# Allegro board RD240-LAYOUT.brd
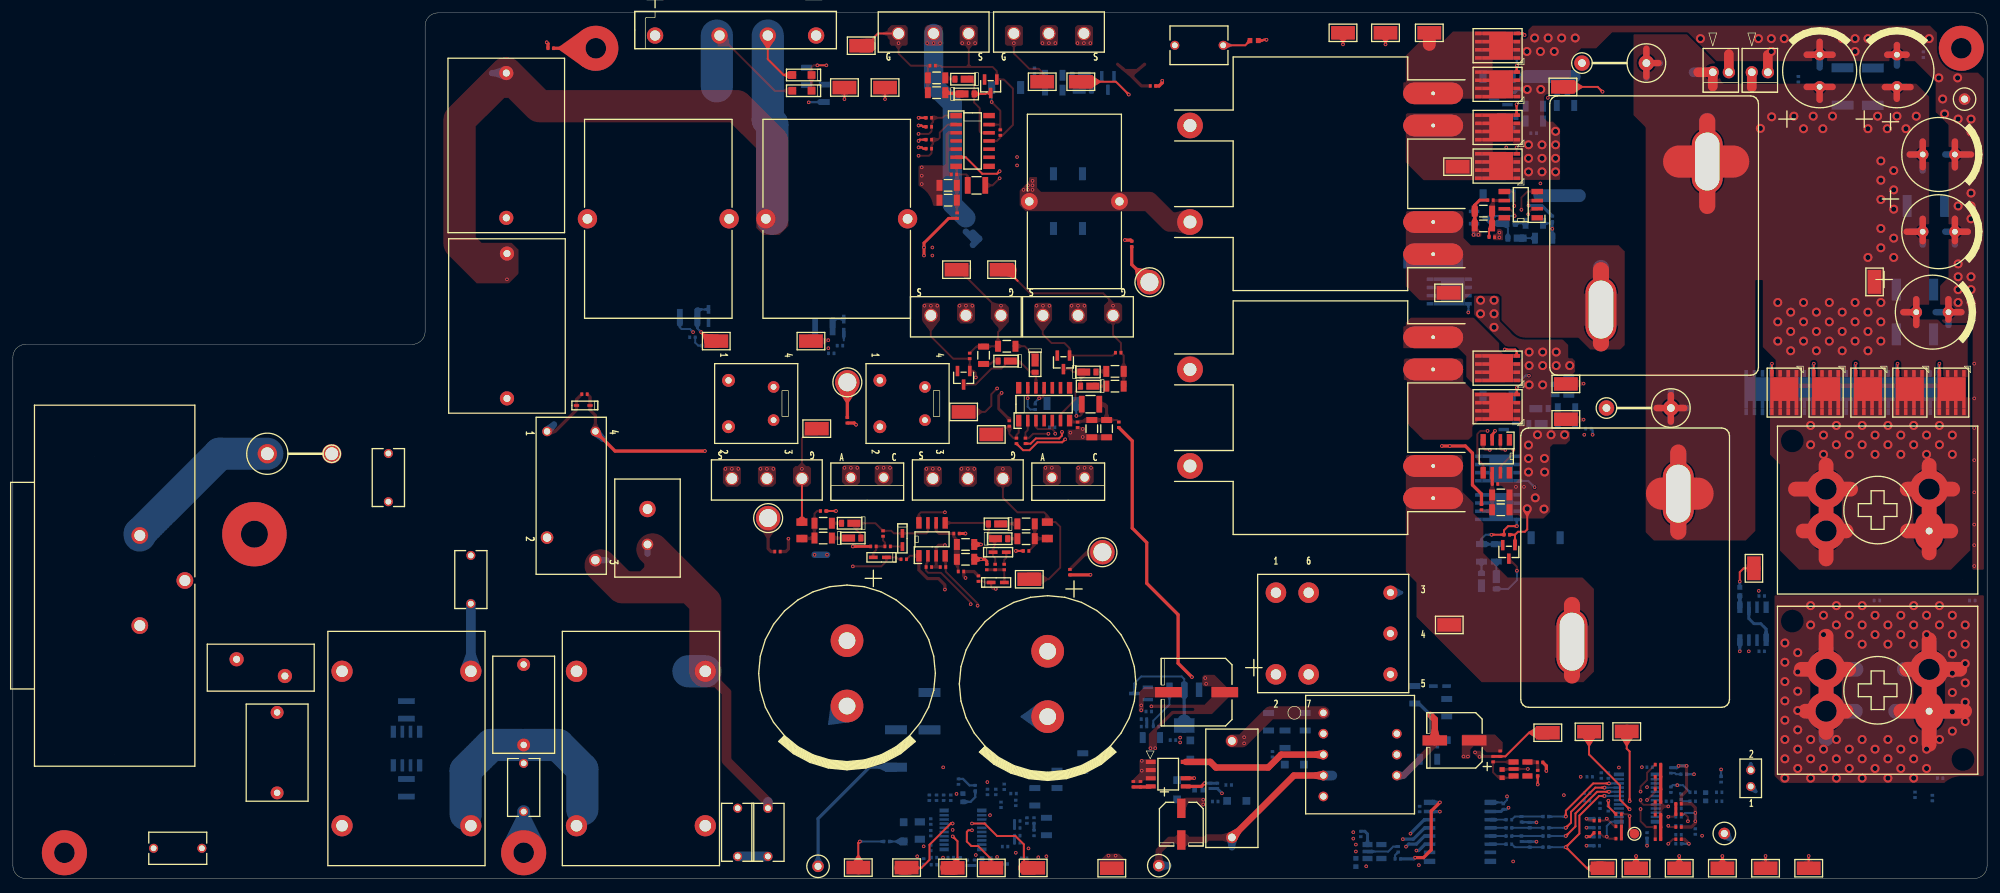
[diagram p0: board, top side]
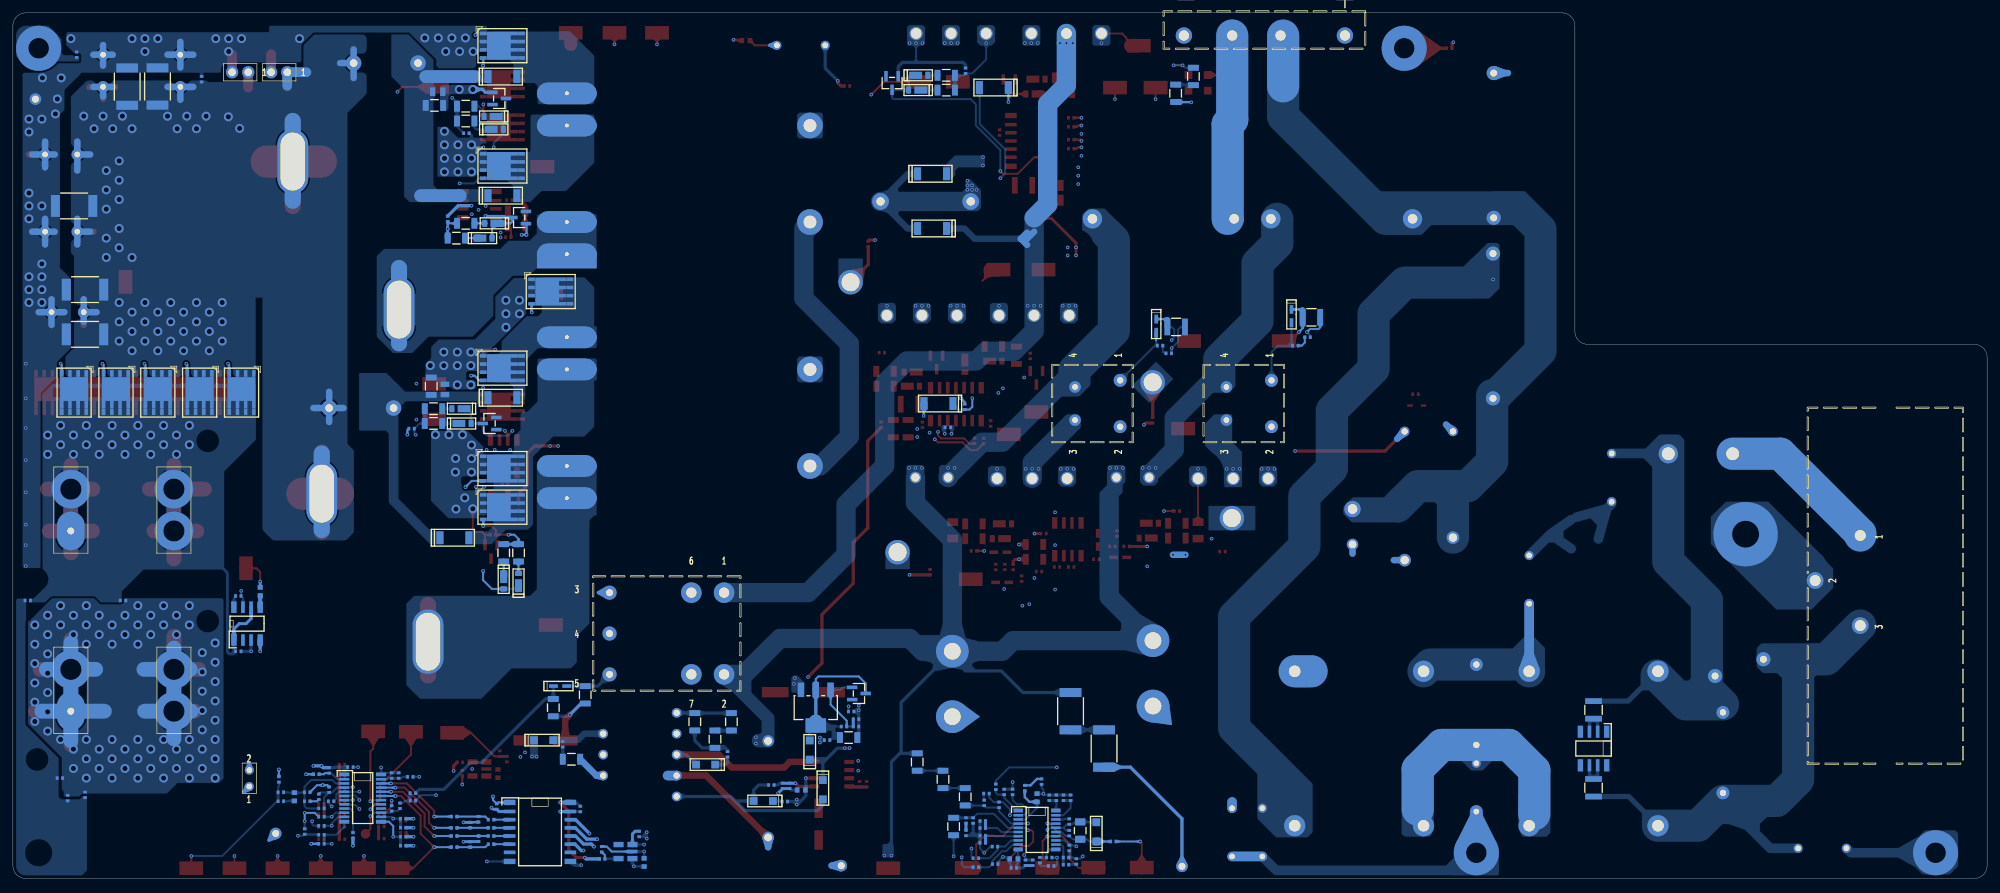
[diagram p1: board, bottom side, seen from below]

Outline 306.5 x 134.5 mm; copper layers: TOP, CONDUCTIVE2, CONDUCTIVE3, CONDUCTIVE4, CONDUCTIVE5, BOTTOM. Coordinates in mm from the lower left corner of the outline.
Outline path: 0,81 0.03,81.35 0.12,81.68 0.27,82 0.47,82.29 0.71,82.53 1,82.73 1.32,82.88 1.65,82.97 2,83 62,83 62.35,83.03 62.68,83.12 63,83.27 63.29,83.47 63.53,83.71 63.73,84 63.88,84.32 63.97,84.65 64,85 64,132.5 64.03,132.85 64.12,133.18 64.27,133.5 64.47,133.79 64.71,134.03 65,134.23 65.32,134.38 65.65,134.47 66,134.5 304.5,134.5 304.85,134.47 305.18,134.38 305.5,134.23 305.79,134.03 306.03,133.79 306.23,133.5 306.38,133.18 306.47,132.85 306.5,132.5 306.5,2 306.47,1.65 306.38,1.32 306.23,1 306.03,0.71 305.79,0.47 305.5,0.27 305.18,0.12 304.85,0.03 304.5,0 2,0 1.65,0.03 1.32,0.12 1,0.27 0.71,0.47 0.47,0.71 0.27,1 0.12,1.32 0.03,1.65 0,2 0,81

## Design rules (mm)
constraint set DEFAULT: 

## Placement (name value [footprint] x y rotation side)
C1  -  [LOCAL_DC215N]  160.65 25.15 90 top
C2  -  [FTP_13]  280.5 128 270 top
C3  -  [FTP_13]  292.5 128 270 top
C4  -  [FTP_13]  301.5 112.5 180 top
C5  -  [FTP_13]  301.5 100.5 180 top
C6  -  [FTP_13]  300.5 88 180 top
C7  -  [LOCAL_DC215N]  129.5 26.8 90 top
C18  -  [FTP_65]  153.3 115.9 90 top
C19  -  [FTP_65#2]  158.72 73.29 90 bottom
C20  -  [FTP_67#2]  262.8 12.7 90 bottom
C21  -  [FTP_65#2]  259 12.7 270 bottom
C22  -  [FTP_65#2]  258.6 10.9 0 bottom
C23  -  [FTP_65#2]  246.6 16 90 bottom
C24  -  [FTP_65#2]  247.7 16 90 bottom
C25  -  [FTP_65#2]  257.1 12 0 bottom
C26  -  [FTP_65#2]  247.7 10.9 90 bottom
C27  -  [DC810K]  240.55 122.25 180 bottom
C30  -  [FTP_73]  41.02 19.56 90 top
C31  -  [LOCAL_DE2E3SA222MN3AT02F]  79.3 10.4 90 top
C32  -  [LOCAL_DE2E3SA222MN3AT02F]  71.1 50.2 270 top
C33  -  [FTP_75]  76.6 113.9 270 top
C34  -  [FTP_65#2]  127.05 81.6 180 bottom
C35  -  [FTP_65]  151.2 48.4 270 top
C36  -  [FTP_65#2]  105.5 84.1 180 bottom
C37  -  [FTP_65]  133.6 51.6 0 top
C38  -  [FTP_65#2]  157.42 9.01 270 bottom
C39  -  [FTP_65#2]  153.4 11.45 90 bottom
C40  -  [FTP_67#2]  147.5 12.55 90 bottom
C41  -  [FTP_66]  149.4 14.05 90 bottom
C42  -  [FTP_65#2]  142.5 4.75 270 bottom
C43  -  [FTP_65#2]  143 3.25 180 bottom
C44  -  [FTP_65#2]  143 2.15 180 bottom
C45  -  [FTP_65#2]  145.6 3.25 180 bottom
C46  -  [FTP_65#2]  147.06 2.85 270 bottom
C47  -  [FTP_65#2]  142.5 7.05 90 bottom
C48  -  [FTP_24]  140.8 7.45 90 bottom
C49  -  [FTP_65#2]  142.5 8.85 270 bottom
C50  -  [FTP_65#2]  152.6 13.45 90 bottom
C51  -  [DC810K]  239.43 76 90 bottom
C52  -  [FTP_73]  79.3 27 90 top
C53  -  [FTP_65]  142.2 114.8 0 top
C54  -  [FTP_65]  142.2 118.2 0 top
C55  -  [FTP_65]  146.1 109.4 0 top
C56  -  [FTP_65#2]  161.35 70.1 0 bottom
C57  -  [FTP_65]  154.7 70.7 270 top
C58  -  [FTP_65]  165.3 70.5 90 top
C59  -  [FTP_65#2]  271.5 43.9 0 bottom
C60  -  [FTP_65]  230.1 61.3 180 top
C61  -  [FTP_65]  229.4 105.4 0 top
C62  -  [FTP_65]  146.5 53.6 180 top
C63  -  [LOCAL_DE2E3SA222MN3AT02F]  112.52 3.43 90 top
C64  -  [LOCAL_DE2E3SA222MN3AT02F]  117.22 3.43 90 top
C65  -  [FTP_75]  76.71 85.85 270 top
C66  -  [FTP_67#2]  208.5 2.5 90 bottom
C67  -  [FTP_65#2]  215.08 4.54 90 bottom
C70  -  [FTP_65]  88.75 75.25 0 top
C75  -  [FTP_65#2]  154.04 4.96 0 bottom
C76  -  [FTP_65#2]  154 2.25 180 bottom
C77  -  [FTP_67#2]  151.1 3.05 0 bottom
C78  -  [LOCAL_DE2E3SA222MN3AT02F]  58.29 58.55 90 top
C79  -  [LOCAL_DE2E3SA222MN3AT02F]  21.84 4.7 0 top
C80  -  [FTP_65]  144.4 48.4 0 top
C81  -  [FTP_65]  142.2 48.4 180 top
C82  -  [FTP_15]  147.9 51.9 180 top
C83  -  [FTP_15]  147.9 49.6 180 top
C84  -  [FTP_15]  167.5 69.9 90 top
C85  -  [FTP_15]  169.8 69.9 90 top
C86  -  [FTP_15]  145.2 105.4 0 top
C87  -  [FTP_15]  145.2 107.7 0 top
C88  -  [FTP_15]  228.3 103.7 0 top
C89  -  [FTP_15]  228.3 101.4 0 top
C90  -  [FTP_15]  231 57.3 180 top
C91  -  [FTP_15]  231 59.6 180 top
C92  -  [FTP_65#2]  289.4 43.2 180 bottom
C93  -  [FTP_65#2]  304.2 43.2 0 bottom
C94  -  [FTP_65#2]  295.3 13 90 bottom
C99  -  [FTP_65#2]  254.1 17.3 180 bottom
C100  -  [FTP_65#2]  271.5 35.3 180 bottom
C101  -  [SIK00180ATP]  180.39 129.46 0 top
C102  -  [FTP_65#2]  277.2 124.2 90 bottom
C103  -  [FTP_65#2]  218.4 10.8 270 bottom
C104  -  [FTP_65#2]  231.38 11.18 270 bottom
C800  -  [LOCAL_ECWF6104JL]  189.25 6.4 90 top
C801  -  [FTP_15]  200.63 24.36 90 bottom
C802  -  [FTP_67#2]  184.1 13.75 0 bottom
C803  -  [DC843C]  181.4 8.45 90 top
C804  -  [DC845R0AKP]  183.77 28.96 0 top
C805  -  [FTP_65#2]  175.6 24.76 180 bottom
C806  -  [FTP_15]  176.75 21.9 0 bottom
C808  -  [FTP_65#2]  176.35 25.95 180 bottom
C815  -  [FTP_65#2]  221.15 20.85 270 bottom
C816  -  [DC837K]  223.81 21.46 0 top
C817  -  [FTP_67]  231.2 16.3 270 top
C818  -  [FTP_65]  236.73 16.38 90 top
CN1  -  [FTP_9]  3.9 45.5 270 top
CN6  -  [FTP_92]  289.5 57.25 90 top
CN7  -  [FTP_92]  289.5 29.25 90 top
CN8  -  [FTP_3]  263.91 125.27 0 top
CN9  -  [FTP_3]  269.96 125.27 0 top
CN10  -  [FTP_7]  269.8 14.3 0 top
D1  -  [DD504V]  130.1 62.31 0 top
D2  -  [DD504V]  161.3 62.31 0 top
D3  -  [FTP_18]  99.7 130.98 0 top
D8  -  [MMK01670AKP]  122.5 122.4 0 top
D9  -  [MMK01670AKP]  122.5 124.85 0 top
D12  -  [FTP_20]  129 85.9 90 bottom
D13  -  [FTP_20]  108 87.4 90 bottom
D14  -  [FTP_20]  221.55 29.9 0 bottom
D16  -  [FTP_81]  154.2 122.9 180 bottom
D17  -  [FTP_81]  162.8 73.8 180 bottom
D18  -  [FTP_81]  163.8 109.5 0 bottom
D19  -  [FTP_81]  163.8 101 180 bottom
D20  -  [FTP_81]  230.5 106.1 0 bottom
D21  -  [FTP_81]  230.5 124.6 0 bottom
D22  -  [FTP_27]  170 123.6 0 bottom
D23  -  [FTP_27]  151.8 123.1 180 top
D24  -  [FTP_27]  147.6 77.8 180 top
D25  -  [FTP_27]  163.1 80.2 180 top
D26  -  [FTP_27]  227.9 102.7 90 bottom
D27  -  [FTP_27]  231 121.2 270 bottom
D28  -  [FTP_27]  232.5 70.7 90 bottom
D29  -  [FTP_27]  232.25 50.75 180 top
D30  -  [FTP_20]  153.2 50.7 180 top
D31  -  [FTP_20]  152.9 46 180 top
D32  -  [FTP_20]  138.1 52.6 90 top
D33  -  [FTP_20]  134.6 49.9 0 top
D34  -  [FTP_81]  237.95 52.95 0 bottom
D35  -  [FTP_81]  230.5 74.7 0 bottom
D36  -  [US2H_A]  152.7 55.1 180 top
D37  -  [US2H_A]  153.2 52.8 0 top
D38  -  [US2H_A]  130.4 52.9 0 top
D39  -  [US2H_A]  129.9 55.2 180 top
D40  -  [US2H_A]  158.7 79.9 270 top
D41  -  [US2H_A]  154.2 80.4 180 top
D42  -  [US2H_A]  148 121.9 0 top
D43  -  [US2H_A]  147.5 124.2 180 top
D44  -  [US2H_A]  167 76.5 180 top
D45  -  [US2H_A]  166.9 78.7 0 top
D46  -  [US2H_A]  166.2 122.5 0 bottom
D47  -  [US2H_A]  165.7 124.8 180 bottom
D48  -  [FTP_28]  88.55 73.5 0 top
D49  -  [FTP_85]  138.3 7.25 270 bottom
D51  -  [US2H_A]  231.6 116.4 180 bottom
D52  -  [US2H_A]  232.1 118.4 0 bottom
D53  -  [US2H_A]  233.35 99.5 180 bottom
D54  -  [US2H_A]  232 101.8 0 bottom
D55  -  [US2H_A]  236.6 70.7 180 bottom
D56  -  [US2H_A]  237.1 73 0 bottom
D57  -  [US2H_A]  230.3 46.25 270 bottom
D58  -  [US2H_A]  228 46.15 90 bottom
D80  -  [MMK01670AKP]  198.95 17.7 180 bottom
D81  -  [MMK01670AKP]  190 12.05 180 bottom
D82  -  [MMK01670AKP]  180.75 13.8 90 bottom
D83  -  [MMK01670AKP]  182.79 19.96 270 bottom
D84  -  [FTP_27]  175.15 28.75 270 bottom
D90  -  [MMK01670AKP]  224.1 21.5 0 bottom
F1  -  [FTP_79]  39.5 66 0 top
FB1  -  [FTP_55]  160.6 54.1 90 top
FB2  -  [FTP_55]  122.5 54.1 90 top
HS1  -  [FTP_116]  129.55 77.1 0 top
HS2  -  [FTP_116]  169.15 50.7 0 top
HS3  -  [FTP_116]  117.25 56 0 top
HS4  -  [FTP_116]  176.45 92.65 0 top
IC1  -  [FTP_60]  61.1 20.2 180 bottom
IC2  -  [FTP_112]  142.7 52.7 0 top
IC3  -  [FTP_128]  147.5 7.55 270 bottom
IC4  -  [FTP_59]  160.1 73.7 0 top
IC5  -  [FTP_59]  149 114.6 270 top
IC6  -  [FTP_112]  234.1 104.7 90 top
IC7  -  [FTP_112]  230.3 65.6 180 top
IC8  -  [FTP_112]  270.15 39.6 180 bottom
IC10  -  [FTP_61]  252.2 12.5 90 bottom
IC11  -  [DI8G1K#2]  211.39 4.19 270 bottom
IC12  -  [LOCAL_I8K0A8]  224.66 7.24 90 bottom
IC20  -  [LOCAL_G5PZ_1A]  82.93 69.47 270 top
IC80  -  [LOCAL_UCC28910_A]  179.37 16.21 0 top
IC81  -  [MM01320AKP]  181.85 26.55 180 bottom
IC82  -  [DI8G1K]  234.06 17.02 270 top
L1  -  [FTP_118]  100.2 102.5 270 top
L2  -  [FTP_118]  127.9 102.5 270 top
L3  -  [FTP_69]  164.8 105.2 270 top
L5  -  [LOCAL_CTW_67A3_3UH]  250.3 48.3 90 top
L6  -  [LOCAL_CTW_67A3_3UH]  254.8 99.9 90 top
L11  -  [FTP_110]  61.1 20.2 270 top
L12  -  [FTP_110]  97.5 20.2 270 top
NOREF  -  []  187.1 98.25 90 top
NOREF#2  -  []  216 11.05 90 top
NOREF#3  -  []  183.4 59.6 0 top
NOREF#4  -  []  183.4 74.6 0 top
NOREF#5  -  []  183.4 68.6 0 top
NOREF#6  -  []  217.6 13.8 45 top
NOREF#7  -  []  186.1 67.6 135 top
NOREF#8  -  []  186.1 120.5 135 top
NOREF#9  -  []  187.1 64.1 90 top
NOREF#10  -  []  183.4 106.5 0 top
NOREF#11  -  []  197.25 50.6 0 top
NOREF#12  -  []  183.4 83.6 0 top
NOREF#13  -  []  221.85 15.4 0 top
NOREF#14  -  []  183.4 121.5 0 top
NOREF#15  -  []  186.1 60.6 45 top
NOREF#16  -  []  186.1 75.6 45 top
NOREF#17  -  []  187.1 79.1 90 top
NOREF#18  -  []  187.1 117 90 top
NOREF#19  -  []  183.4 112.5 0 top
NOREF#20  -  []  186.1 113.5 45 top
NOREF#21  -  []  186.1 105.5 135 top
NOREF#22  -  []  186.1 82.6 135 top
Q1  -  [RDP10020ATP]  122.5 62.15 180 top
Q2  -  [RDP10020ATP]  153.7 62.15 180 top
Q3  -  [RDP10020ATP]  153.4 87.5 180 top
Q4  -  [RDP10020ATP]  170.8 87.5 180 top
Q5  -  [RDP10020ATP]  137.5 131.3 0 top
Q6  -  [RDP10020ATP]  155.4 131.3 0 top
Q7  -  [LOCAL_SNP100F0AKP]  230.5 79.3 90 top
Q8  -  [LOCAL_SNP100F0AKP]  223 91.2 270 bottom
Q9  -  [LOCAL_SNP100F0AKP]  230.5 57.7 270 bottom
Q10  -  [LOCAL_SNP100F0AKP]  230.5 63.7 270 bottom
Q11  -  [LOCAL_SNP100F0AKP]  230.5 129.4 90 top
Q12  -  [LOCAL_SNP100F0AKP]  230.5 123.4 90 top
Q13  -  [LOCAL_SNP100F0AKP]  230.5 116.7 90 top
Q14  -  [LOCAL_SNP100F0AKP]  230.5 110.7 270 bottom
Q15  -  [LOCAL_SNP100F0AKP]  301 75.5 180 top
Q16  -  [LOCAL_SNP100F0AKP]  294.5 75.5 180 top
Q17  -  [LOCAL_SNP100F0AKP]  288 75.5 180 top
Q18  -  [LOCAL_SNP100F0AKP]  281.5 75.5 180 top
Q19  -  [LOCAL_SNP100F0AKP]  275 75.5 180 top
Q20  -  [LOCAL_SNP100F0AKP]  297 75.5 0 bottom
Q21  -  [LOCAL_SNP100F0AKP]  290.5 75.5 0 bottom
Q22  -  [LOCAL_SNP100F0AKP]  284 75.5 0 bottom
Q23  -  [LOCAL_SNP100F0AKP]  277.5 75.5 0 bottom
Q24  -  [LOCAL_SNP100F0AKP]  271 75.5 0 bottom
Q25  -  [LOCAL_SNP100F0AKP]  230.5 129.4 270 bottom
Q26  -  [LOCAL_SNP100F0AKP]  230.5 110.7 90 top
Q27  -  [LOCAL_SNP100F0AKP]  230.5 73.3 90 top
Q28  -  [LOCAL_SNP100F0AKP]  230.5 79.3 270 bottom
R1  -  [FTP_50#2]  160.45 8.08 90 bottom
R2  -  [KC00050AKP#2]  158.53 7.08 270 bottom
R6  -  [FTP_67#2]  268.1 44.6 270 bottom
R7  -  [FTP_49#2]  104.9 87.2 180 bottom
R8  -  [FTP_49#2]  125.9 85.7 180 bottom
R9  -  [FTP_50#2]  217.64 28.55 270 bottom
R18  -  [FTP_50#2]  236.2 117.7 180 bottom
R19  -  [KC00050AKP#2]  236.1 115.8 180 bottom
R20  -  [FTP_50#2]  237.65 99.5 180 bottom
R21  -  [KC00050AKP#2]  239 102.5 90 bottom
R22  -  [KC00050AKP#2]  244.6 69.9 0 bottom
R23  -  [FTP_50#2]  241.2 70.7 180 bottom
R24  -  [FTP_50#2]  230.3 50.6 270 bottom
R25  -  [KC00050AKP]  231.93 53.42 180 top
R28  -  [KC00050AKP]  142.8 126.3 180 top
R29  -  [KC00050AKP#2]  158.6 125.5 90 bottom
R31  -  [KC00050AKP]  148.55 81.2 90 top
R33  -  [KC00050AKP]  171.6 81.7 0 top
R42  -  [KC00050AKP#2]  264.9 13.4 180 bottom
R43  -  [KC00050AKP#2]  260.8 13.4 180 bottom
R44  -  [KC00050AKP#2]  257.4 16.8 270 bottom
R45  -  [KC00050AKP#2]  259.4 16.2 0 bottom
R46  -  [KC00050AKP#2]  264.9 12 180 bottom
R47  -  [KC00050AKP#2]  260.8 12 180 bottom
R48  -  [KC00050AKP#2]  257.4 13.8 90 bottom
R49  -  [KC00050AKP#2]  244.8 15.8 180 bottom
R50  -  [KC00050AKP]  255.4 17.7 180 top
R51  -  [KC00050AKP]  255.4 9.9 180 top
R52  -  [KC00050AKP]  255.4 13.9 180 top
R53  -  [KC00050AKP]  255.4 8 180 top
R54  -  [KC00050AKP#2]  253.7 6.7 270 bottom
R55  -  [KC00050AKP]  258.6 10 180 top
R56  -  [KC00050AKP#2]  258.6 8.2 0 bottom
R57  -  [KC00050AKP#2]  258.6 9.6 180 bottom
R58  -  [KC00050AKP]  258.6 8 0 top
R59  -  [KC00050AKP#2]  244.4 12.1 180 bottom
R60  -  [KC00050AKP#2]  258.6 6.8 180 bottom
R61  -  [KC00050AKP#2]  258.6 5.4 0 bottom
R62  -  [KC00050AKP#2]  261.2 7.3 270 bottom
R63  -  [KC00050AKP]  249.3 6.2 0 top
R64  -  [KC00050AKP#2]  245.9 6.5 180 bottom
R65  -  [KC00050AKP]  249.3 8.1 0 top
R66  -  [KC00050AKP#2]  245.9 9.3 180 bottom
R67  -  [KC00050AKP#2]  244.41 13.26 0 bottom
R69  -  [KC00050AKP#2]  246.4 11.3 270 bottom
R70  -  [KC00050AKP]  249.3 10 0 top
R71  -  [KC00050AKP]  157.3 50.9 0 top
R72  -  [FTP_50]  157.3 55.1 0 top
R73  -  [KC00050AKP]  125.8 57.1 180 top
R74  -  [FTP_50]  125.8 52.9 180 top
R75  -  [KC00050AKP#2]  265.2 15.4 270 bottom
R76  -  [FTP_50#2]  241.05 120.12 180 bottom
R77  -  [FTP_98]  253.6 126.7 180 top
R79  -  [FTP_49#2]  61.1 26.2 270 bottom
R80  -  [FTP_49#2]  61.1 14.1 270 bottom
R81  -  [KC00050AKP#2]  128.4 82.8 180 bottom
R82  -  [KC00050AKP]  152.5 48.4 270 top
R83  -  [KC00050AKP]  149.9 46.6 90 top
R85  -  [KC00050AKP#2]  107.4 82.8 180 bottom
R86  -  [KC00050AKP]  135.1 53.6 270 top
R87  -  [KC00050AKP]  138.3 49.6 0 top
R89  -  [FTP_50#2]  158.65 12.7 270 bottom
R90  -  [KC00050AKP#2]  155.35 13.2 180 bottom
R91  -  [FTP_50#2]  162.1 15.4 270 bottom
R92  -  [FTP_50#2]  166.1 18.1 270 bottom
R93  -  [KC00050AKP#2]  146.8 15.05 270 bottom
R94  -  [FTP_50#2]  125.98 122 270 bottom
R95  -  [FTP_50#2]  123.22 124.62 270 bottom
R96  -  [KC00050AKP#2]  151.1 1.65 0 bottom
R97  -  [KC00050AKP#2]  149.3 2.45 270 bottom
R98  -  [KC00050AKP#2]  141.4 2.65 90 bottom
R99  -  [KC00050AKP#2]  145.3 1.95 180 bottom
R100  -  [KC00050AKP#2]  143.4 12.55 90 bottom
R101  -  [KC00050AKP#2]  155.94 5.55 0 bottom
R102  -  [KC00050AKP#2]  155.93 7.84 0 bottom
R103  -  [KC00050AKP#2]  145.6 12.55 90 bottom
R104  -  [KC00050AKP#2]  151.3 13.45 90 bottom
R105  -  [FTP_50#2]  241.55 76.5 90 bottom
R106  -  [FTP_98]  257.4 73.1 180 top
R108  -  [FTP_50]  157.3 52.8 0 top
R109  -  [FTP_50]  125.8 55.2 180 top
R110  -  [KC00050AKP]  142.2 113.4 0 top
R111  -  [KC00050AKP]  142.2 116.8 0 top
R112  -  [KC00050AKP]  157.2 68 90 top
R113  -  [KC00050AKP]  155.8 68 90 top
R114  -  [FTP_49]  149.6 107.7 0 top
R115  -  [FTP_49]  167.3 73.7 180 top
R116  -  [KC00050AKP#2]  209.26 6.92 270 bottom
R117  -  [KC00050AKP#2]  215.01 3.05 180 bottom
R120  -  [KC00050AKP#2]  135.65 5.76 180 bottom
R121  -  [KC00050AKP]  147.2 47.7 180 top
R122  -  [KC00050AKP]  171.7 70.5 90 top
R123  -  [KC00050AKP]  146.6 103 90 top
R124  -  [KC00050AKP]  228 57.7 270 top
R125  -  [KC00050AKP]  229.6 99.65 180 top
R126  -  [FTP_50]  154.3 82.7 180 top
R127  -  [FTP_50]  150.7 81.3 90 top
R132  -  [FTP_50]  143.4 122.1 180 top
R133  -  [FTP_50]  143.4 124.4 180 top
R134  -  [FTP_50]  171.1 76.5 0 top
R135  -  [FTP_50]  171.1 78.8 0 top
R136  -  [FTP_50#2]  161.6 122.5 0 bottom
R137  -  [FTP_50#2]  161.6 124.8 0 bottom
R138  -  [DR0127]  98.52 51.91 90 top
R169  -  [KC00050AKP#2]  157 3.15 0 bottom
R170  -  [KC00050AKP#2]  157 1.75 0 bottom
R171  -  [KC00050AKP#2]  153.9 14.25 270 bottom
R172  -  [KC00050AKP]  153.9 48.4 270 top
R173  -  [KC00050AKP]  135.8 51.6 180 top
R174  -  [KC00050AKP#2]  144.5 12.55 90 bottom
R175  -  [KC00050AKP#2]  155.93 8.94 0 bottom
R176  -  [KC00050AKP#2]  155.93 6.66 0 bottom
R177  -  [KC00050AKP#2]  148.17 2.45 270 bottom
R178  -  [FTP_106]  142.3 26 270 bottom
R179  -  [FTP_106]  137.1 20.2 270 bottom
R180  -  [KC00050AKP]  255.4 11.9 180 top
R181  -  [KC00050AKP]  255.4 15.8 180 top
R182  -  [KC00050AKP]  255.4 6.1 180 top
R184  -  [KC00050AKP]  258.6 6.1 180 top
R185  -  [FTP_50#2]  222.6 26.55 270 bottom
R198  -  [KC00050AKP#2]  142.28 12.55 90 bottom
R199  -  [FTP_106]  295.3 84.55 0 bottom
R200  -  [FTP_106]  284.05 123.06 90 bottom
R201  -  [FTP_106]  288.75 123.04 90 bottom
R202  -  [FTP_106]  295.3 91.5 0 bottom
R203  -  [FTP_106]  297 104.5 0 bottom
R204  -  [KC00050AKP#2]  296.6 128 270 bottom
R205  -  [KC00050AKP#2]  299.2 15.6 0 bottom
R206  -  [KC00050AKP#2]  298 12.5 270 bottom
R207  -  [KC00050AKP]  258.6 11.6 0 top
R208  -  [KC00050AKP]  245.9 7.1 0 top
R209  -  [KC00050AKP]  245.9 9 0 top
R210  -  [KC00050AKP#2]  245.9 5.1 0 bottom
R211  -  [KC00050AKP#2]  245.9 7.9 0 bottom
R212  -  [FTP_50#2]  236.2 120 180 bottom
R213  -  [FTP_50#2]  236.2 101.8 180 bottom
R214  -  [FTP_50#2]  241.2 73 180 bottom
R215  -  [FTP_50#2]  228 50.6 270 bottom
R220  -  [KC00050AKP]  129.55 71.2 90 top
R221  -  [KC00050AKP]  164.1 47.6 90 top
R222  -  [KC00050AKP]  118.7 50.8 180 top
R223  -  [KC00050AKP]  173.7 98.6 270 top
R224  -  [KC00050AKP]  177 123.15 180 top
R225  -  [KC00050AKP]  83.5 129 0 top
R227  -  [KC00050AKP#2]  155.7 11.75 90 bottom
R228  -  [KC00050AKP#2]  158.53 9.02 270 bottom
R800  -  [FTP_50#2]  194.95 24.35 270 bottom
R801  -  [FTP_50#2]  197.5 21.65 270 bottom
R802  -  [KC00050AKP#2]  195.55 19.3 90 bottom
R803  -  [KC00050AKP]  173.95 14.65 270 top
R804  -  [KC00050AKP]  175.05 14.65 270 top
R805  -  [FTP_67]  192.7 130.2 180 top
R806  -  [KC00050AKP#2]  185.9 14.4 270 bottom
R807  -  [KC00050AKP#2]  187 14.4 270 bottom
R808  -  [KC00050AKP#2]  188.75 14.53 180 bottom
R809  -  [KC00050AKP#2]  186.66 11.96 180 bottom
R810  -  [KC00050AKP#2]  177.47 23.61 180 bottom
R811  -  [KC00050AKP#2]  175.61 23.61 180 bottom
R812  -  [FTP_50#2]  219.78 18.53 180 bottom
R813  -  [KC00050AKP]  230.9 19.4 270 top
R814  -  [KC00050AKP]  229.8 18.55 270 top
R815  -  [KC00050AKP]  237.1 18.05 0 top
R816  -  [KC00050AKP#2]  238 9.62 180 bottom
R817  -  [KC00050AKP#2]  234.2 9.2 270 bottom
R819  -  [KC00050AKP#2]  232.27 9.14 0 bottom
R820  -  [KC00050AKP#2]  238 7.87 180 bottom
R821  -  [KC00050AKP#2]  235.5 8.3 90 bottom
R823  -  [KC00050AKP#2]  232.27 7.87 0 bottom
R824  -  [KC00050AKP#2]  238 6.6 180 bottom
R825  -  [KC00050AKP#2]  234.2 6.18 270 bottom
R827  -  [KC00050AKP#2]  232.27 6.6 0 bottom
R828  -  [KC00050AKP#2]  238 4.88 180 bottom
R829  -  [KC00050AKP#2]  235.5 5.3 90 bottom
R831  -  [KC00050AKP#2]  232.27 5.33 0 bottom
R832  -  [KC00050AKP#2]  180.1 21.5 0 bottom
RV1  -  [FTP_120]  38.48 32.77 180 top
T2  -  [FTP_94]  138.9 73.8 270 top
T3  -  [FTP_94]  115.4 73.8 270 top
T4  -  [FTP_96]  204.98 38.07 0 top
T5  -  [FTP_126]  203 71.6 0 top
T6  -  [FTP_126]  203 109.5 0 top
T8  -  [LOCAL_YB_03317A]  203.45 25.75 270 top
TP1  -  [FTP_57]  123.9 83.5 0 top
TP2  -  [FTP_57]  109.2 83.5 0 top
TP3  -  [FTP_57]  157.8 46.5 0 top
TP4  -  [FTP_57]  124.8 69.9 0 top
TP5  -  [FTP_57]  145.9 1.65 0 top
TP6  -  [FTP_57]  138.75 1.7 0 top
TP7  -  [FTP_57]  151.9 1.65 0 top
TP8  -  [FTP_57]  158.4 1.65 0 top
TP9  -  [FTP_57]  151.9 69 0 top
TP10  -  [FTP_57]  147.6 72.5 0 top
TP11  -  [FTP_57]  146.5 94.6 0 top
TP12  -  [FTP_57]  153.5 94.6 0 top
TP13  -  [FTP_57]  131.7 129.4 0 top
TP14  -  [FTP_57]  159.8 123.8 180 top
TP15  -  [FTP_57]  165.8 123.8 0 top
TP17  -  [FTP_57]  222.9 91 0 top
TP18  -  [FTP_57]  223 39.4 180 top
TP19  -  [FTP_57]  240.65 123 180 top
TP20  -  [FTP_57]  241.1 71.35 0 top
TP21  -  [FTP_57]  213.1 131.4 0 top
TP22  -  [FTP_57]  241.1 76.85 0 top
TP23  -  [FTP_57]  250.55 22.85 0 top
TP24  -  [FTP_57]  244.7 22.8 0 top
TP27  -  [FTP_57]  206.5 131.4 0 top
TP28  -  [FTP_57]  270.3 48.2 90 top
TP29  -  [FTP_57]  224.3 110.6 0 top
TP30  -  [FTP_57]  219.9 131.4 0 top
TP31  -  [FTP_57]  289.02 92.7 90 top
TP32  -  [FTP_57]  272.1 1.6 0 top
TP33  -  [FTP_57]  278.8 1.6 0 top
TP34  -  [FTP_57]  265.4 1.6 0 top
TP35  -  [FTP_57]  252 1.6 0 top
TP36  -  [FTP_57]  258.7 1.6 0 top
TP37  -  [FTP_57]  246.8 1.6 0 top
TP38  -  [FTP_57]  135.4 122.9 0 top
TP39  -  [FTP_57]  129.1 122.9 0 top
TP41  -  [FTP_71]  303 121.1 0 top
TP42  -  [FTP_71]  265.7 7 0 top
TP43  -  [FTP_71]  125 1.9 0 top
TP44  -  [FTP_57]  170.61 1.6 180 top
TP45  -  [FTP_71]  177.9 2 0 top
TP46  -  [DTP815]  251.75 6.95 0 top
TP82  -  [FTP_57]  131.25 1.7 0 top
TP83  -  [FTP_57]  238.3 22.65 0 top

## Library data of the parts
C1 C7 = EKHE451VSN331MQ35Z: alternate symbols: (T:Local_DC215N;B:Local_DC215N_B)
C2-C6 = PRT_3: alternate symbols: (T:FTP_13;B:FTP_14)
C18 C19 C21-C26 C34-C39 C42-C47 C49 C50 C53-C62 C67 C70 C75 C76 C80 C81 C92-C94 C99 C100 C102-C104 C805 C808 C815 C818 = PRT_52: alternate symbols: (T:FTP_65;B:FTP_66)
C20 C40 C66 C77 C802 C817 = PRT_48: alternate symbols: (T:FTP_67;B:FTP_68)
C27 C51 = K0302287: alternate symbols: (T:DC810K;B:DC910K)
C30 C52 = PRT_17: alternate symbols: (T:FTP_73;B:FTP_74)
C31 C32 C63 C64 = DE2E3SA222MN3AT02F: alternate symbols: (T:Local_DE2E3SA222MN3AT02F;B:Local_DE2E3SA222MN3AT02F_B)
C33 C65 = PRT_18: alternate symbols: (T:FTP_75;B:FTP_76)
C41 = PRT_32
C48 = PRT_51: alternate symbols: (T:FTP_24;B:FTP_25)
C78 C79 = DE2B3SA101KA3BT02F
C82-C91 C801 C806 = PRT_46: alternate symbols: (T:FTP_15;B:FTP_16)
C101 = DE2B3SA221KA3BT02F: alternate symbols: (T:SIK00180ATP;B:SIK00180ATP_B)
C800 = ECWF6104JL: alternate symbols: (T:Local_ECWF6104JL;B:Local_ECWF6104JL_B)
C803 = EMLA350ARA220MF61G: alternate symbols: (T:DC843C;B:DC943C)
C804 = EMLA350ARA331MJA0G: alternate symbols: (T:DC845R0AKP;B:DC845R0BKP)
C816 = EMLA250ARA221MHA0G: alternate symbols: (T:DC837K;B:DC937K)
CN1 = PRT_61: alternate symbols: (T:FTP_9;B:FTP_10)
CN6 CN7 = PRT_38: alternate symbols: (T:FTP_92;B:FTP_93)
CN8 CN9 = PRT_42: alternate symbols: (T:FTP_3;B:FTP_4)
CN10 = PRT_56: alternate symbols: (T:FTP_7;B:FTP_8)
D1 D2 = TRS8E65H: alternate symbols: (T:DD504V;B:DD504V_B)
D3 = PRT_53: alternate symbols: (T:FTP_18;B:FTP_88)
D8 D9 = CRG04A: alternate symbols: (T:MMK01670AKP;B:MMK01670BKP)
D12-D14 D30-D33 = PRT_27: alternate symbols: (T:FTP_20;B:FTP_22)
D16-D21 D34 D35 = PRT_14: alternate symbols: (T:FTP_81;B:FTP_82)
D22-D29 D84 = PRT_25: alternate symbols: (T:FTP_27;B:FTP_31)
D36-D47 D51-D58 = CUHS15S30: alternate symbols: (T:US2H_A;B:US2H_B)
D48 = PRT_26: alternate symbols: (T:FTP_28;B:FTP_32)
D49 = PRT_6: alternate symbols: (T:FTP_85;B:FTP_86)
D80 = CRF03A: alternate symbols: (T:MMK01670AKP;B:MMK01670BKP)
D81 D82 D90 = GDM420000387: alternate symbols: (T:MMK01670AKP;B:MMK01670BKP)
D83 = K4200730: alternate symbols: (T:MMK01670AKP;B:MMK01670BKP)
F1 = PRT_21: alternate symbols: (T:FTP_79,F1_FTP_79;B:FTP_80)
FB1 FB2 = PRT_30: alternate symbols: (T:FTP_55;B:FTP_56)
HS1-HS4 = PRT_39: alternate symbols: (T:FTP_116;B:FTP_117)
IC1 = PRT_45: alternate symbols: (T:FTP_60;B:FTP_63)
IC2 IC6 IC7 = PRT_63: alternate symbols: (T:FTP_112;B:FTP_113)
IC3 = PRT_59: alternate symbols: (T:FTP_128;B:FTP_129)
IC4 IC5 = PRT_58: alternate symbols: (T:FTP_59;B:FTP_62)
IC8 = PRT_62: alternate symbols: (T:FTP_112;B:FTP_113)
IC10 = PRT_16: alternate symbols: (T:FTP_61;B:FTP_64)
IC11 IC82 = TCR1HF50B: alternate symbols: (T:DI8G1K;B:DI9G1K)
IC12 = DCL540C01: alternate symbols: (T:Local_I8K0A8;B:LocalI9K0A8)
IC20 = G5PZ-1A: alternate symbols: (T:Local_G5PZ_1A;B:Local_G5PZ_1A_B)
IC80 = UCC28910: alternate symbols: (T:Local_UCC28910_A;B:Local_UCC28910_B)
IC81 = LM317MDCY: alternate symbols: (T:MM01320AKP;B:MM01320BKP)
L1 L2 = PRT_41: alternate symbols: (T:FTP_118;B:FTP_119)
L3 = PRT_64: alternate symbols: (T:FTP_69;B:FTP_70)
L5 L6 = CTW-67A3_3uH: alternate symbols: (T:Local_CTW_67A3_3uH;B:Local_CTW_67A3_3uH_B)
L11 L12 = PRT_22: alternate symbols: (T:FTP_110;B:FTP_111)
Q1 Q2 = TK125N60Z1: alternate symbols: (T:RDP10020ATP;B:RDP10020BTP)
Q3-Q6 = TK095N65Z5: alternate symbols: (T:RDP10020ATP;B:RDP10020BTP)
Q7-Q14 Q25-Q28 = TPH2R408QM(L1Q): alternate symbols: (T:Local_SNP100F0AKP;B:Local_SNP100F0BKP)
Q15-Q24 = TPHR6503PL1(LQ): alternate symbols: (T:Local_SNP100F0AKP;B:Local_SNP100F0BKP)
R1 R9 R18 R20 R23 R24 R72 R74 R76 R89 R91 R92 R94 R95 R105 R108 R109 R126 R127 R132-R137 R185 R212-R215 R800 R801 R812 = PRT_5: alternate symbols: (T:FTP_50;B:FTP_51)
R2 R19 R21 R22 R25 R28 R29 R31 R33 R42-R67 R69-R71 R73 R75 R81-R83 R85-R87 R90 R93 R96-R104 R110-R113 R116 R117 R120-R125 R169-R177 R180-R182 R184 R198 R204-R211 R220-R225 R227 R228 R802-R804 R806-R811 R813-R817 R819-R821 R823-R825 R827-R829 R831 R832 = GDM010004481: alternate symbols: (T:KC00050AKP;B:KC00050BKP)
R6 R805 = PRT_8: alternate symbols: (T:FTP_67;B:FTP_68)
R7 R8 R79 R80 R114 R115 = PRT_23: alternate symbols: (T:FTP_49;B:FTP_52)
R77 R106 = PRT_54: alternate symbols: (T:FTP_98;B:FTP_99)
R138 = A5MC-100JK_L3_5: alternate symbols: (T:DR0127;B:DR0127_B)
R178 R179 R199-R203 = PRT_43: alternate symbols: (T:FTP_106;B:FTP_107)
RV1 = PRT_37: alternate symbols: (T:FTP_120;B:FTP_121)
T2 T3 = PRT_7: alternate symbols: (T:FTP_94;B:FTP_95)
T4 = PRT_65: alternate symbols: (T:FTP_96;B:FTP_97)
T5 T6 = PRT_55: alternate symbols: (T:FTP_126,T5_FTP_126,T6_FTP_126;B:FTP_127)
T8 = YB-03317A: alternate symbols: (T:Local_YB_03317A;B:Local_YB_03317A_B)
TP1-TP15 TP17-TP24 TP27-TP39 TP44 TP82 TP83 = PRT_44: alternate symbols: (T:FTP_57;B:FTP_58)
TP41 TP42 = PRT_34: alternate symbols: (T:FTP_71;B:FTP_72)
TP43 TP45 = PRT_49: alternate symbols: (T:FTP_71;B:FTP_72)
TP46 = DTP815: alternate symbols: (T:DTP815;B:DTP915)

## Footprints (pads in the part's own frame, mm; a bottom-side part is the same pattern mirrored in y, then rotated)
DC810K
  rect 0.83x1.35 smd: 1(0.8,0) 2(-0.8,0)
DC837K
  rect 3.82x1.6 smd: 1(-3.06,0) 2(3.06,0)
DC843C
  rect 3.02x1.3 smd: 1(-2.46,0) 2(2.46,0)
DC845R0AKP
  rect 4.15x1.6 smd: 1(-4.375,0) 2(4.375,0)
DD504V
  round 1.778 hole 1.3: A(0,0) C(5.08,0)
DI8G1K
  rect 0.825x1.56 smd: 1(-1.087,-1.075) 3(1.087,-1.075) 4(1.087,1.075) 5(-1.087,1.075)
  rect 0.55x1.56 smd: 2(0,-1.075)
DI8G1K#2
  rect 0.825x1.56 smd: 1(1.087,1.075) 3(-1.087,1.075) 4(-1.087,-1.075) 5(1.087,-1.075)
  rect 0.55x1.56 smd: 2(0,1.075)
DR0127
  round 1.778 hole 1.2: 1(0,0)
  round 2.54 hole 1.5: 2(5.5,0)
DTP815
  round 1.5 smd: 1(0,0)
FTP_3
  round 1.9 hole 1.2: 1(0,0) 2(2.5,0)
FTP_7
  round 1.4 hole 0.9: 1(0,0) 2(0,2.54)
FTP_9
  round 0.01 hole 2.6x4 unplated: (-26.2,11.8) (26.2,11.8)
  round 0.01 hole 3.6 unplated: (-20.05,8.75) (20.05,8.75)
  round 2.6 hole 1.7: 1(-7.8,15.8) 2(-0.8,22.8) 3(6.2,15.8)
FTP_13
  round 1.8 hole 0.9: 1(0,0) 2(5,0)
FTP_15
  rect 0.92x1.7 smd: 1(-1.35,0) 2(1.35,0)
FTP_18
  round 2.54 hole 1.6: 1(0,0) 2(10,0) 3(17.5,0) 4(25,0)
FTP_20
  rect 1.36x0.55 smd: A(-1.025,0) C(1.025,0)
FTP_24
  rect 1.1x1.6 smd: 1(1.35,0) 2(-1.35,0)
FTP_27
  rect 0.55x1.61 smd: A(-0.95,-1.05) C(0,1.05) NC(0.95,-1.05)
FTP_28
  rect 0.824x0.4 smd: A(-1.05,0) C(1.05,0)
FTP_49
  rect 0.895x2.6 smd: 1(-1.363,0) 2(1.363,0)
FTP_49#2
  rect 0.895x2.6 smd: 1(1.363,0) 2(-1.363,0)
FTP_50
  rect 0.92x1.7 smd: 1(-1.35,0) 2(1.35,0)
FTP_50#2
  rect 0.92x1.7 smd: 1(1.35,0) 2(-1.35,0)
FTP_55
  rect 1.17x1.7 smd: 1(-1.275,0) 2(1.275,0)
FTP_57
  rect 3.7x2.1 smd: 1(0,0)
FTP_59
  rect 0.825x1.805 smd: 1(-3.947,-2.553) 7(3.947,-2.553) 8(3.947,2.553) 14(-3.947,2.553)
  rect 0.55x1.805 smd: 2(-2.54,-2.553) 3(-1.27,-2.553) 4(0,-2.553) 5(1.27,-2.553) 6(2.54,-2.553) 9(2.54,2.553) 10(1.27,2.553) 11(0,2.553) 12(-1.27,2.553) 13(-2.54,2.553)
FTP_60
  rect 0.825x1.885 smd: 1(2.042,2.612) 4(-2.042,2.612) 5(-2.042,-2.612) 8(2.042,-2.612)
  rect 0.55x1.885 smd: 2(0.635,2.612) 3(-0.635,2.612) 6(-0.635,-2.612) 7(0.635,-2.612)
FTP_61
  rect 0.6x1.585 smd: 1(3.675,2.862) 12(-3.675,2.862) 13(-3.675,-2.862) 24(3.675,-2.862)
  rect 0.4x1.585 smd: 2(2.925,2.862) 3(2.275,2.862) 4(1.625,2.862) 5(0.975,2.862) 6(0.325,2.862) 7(-0.325,2.862) 8(-0.975,2.862) 9(-1.625,2.862) 10(-2.275,2.862) 11(-2.925,2.862) 14(-2.925,-2.862) 15(-2.275,-2.862) 16(-1.625,-2.862) 17(-0.975,-2.862) 18(-0.325,-2.862) 19(0.325,-2.862) 20(0.975,-2.862) 21(1.625,-2.862) 22(2.275,-2.862) 23(2.925,-2.862)
FTP_65
  rect 0.45x0.55 smd: 1(-0.425,0) 2(0.425,0)
FTP_65#2
  rect 0.45x0.55 smd: 1(0.425,0) 2(-0.425,0)
FTP_66
  rect 0.45x0.55 smd: 1(0.425,0) 2(-0.425,0)
FTP_67
  rect 0.72x0.8 smd: 1(-0.64,0) 2(0.64,0)
FTP_67#2
  rect 0.72x0.8 smd: 1(0.64,0) 2(-0.64,0)
FTP_69
  round 2.6 hole 1.3: 1(0,-7) 2(0,7)
FTP_71
  round 1.8 hole 1.1: 1(0,0)
FTP_73
  round 2 hole 1: 1(-6.25,0) 2(6.25,0)
FTP_75
  round 2.2 hole 1.1: 1(-11.25,0) 2(11.25,0)
FTP_79
  round 3 hole 2: 1(0,0) 2(10,0)
FTP_81
  rect 1.1x2 smd: A(-2.25,0) C(2.25,0)
FTP_85
  rect 1.212x1.2 smd: A(-1.494,0) C(1.494,0)
FTP_92
  round 0.01 hole 2.5 unplated: (-10.75,-13.25) (10.75,13.25)
  custom 1.075x1.075 hole 5x3.3: 1(-3.25,-8)
FTP_94
  round 2 hole 1: 1(-3.6,-4.3) 2(3.6,-4.3)
  round 1.8 hole 0.9: 3(2.575,2.7) 4(-2.575,2.7)
FTP_96
  round 3.2 hole 1.6: 1(-8.89,6.35) 2(-8.89,-6.35) 6(-3.81,6.35) 7(-3.81,-6.35)
  round 2.2 hole 1.1: 3(8.89,6.35) 4(8.89,0) 5(8.89,-6.35)
FTP_98
  round 2.4 hole 1.2: 1(0,0) 2(10,0)
FTP_106
  rect 1.405x3.4 smd: 1(2.902,0) 2(-2.902,0)
FTP_110
  round 3.3 hole 1.8: 1(-12,10) 2(-12,-10) 3(12,-10) 4(12,10)
FTP_112
  rect 0.825x1.795 smd: 1(-2.042,-2.558) 4(2.042,-2.558) 5(2.042,2.558) 8(-2.042,2.558)
  rect 0.55x1.795 smd: 2(-0.635,-2.558) 3(0.635,-2.558) 6(0.635,2.558) 7(-0.635,2.558)
FTP_116
  round 3.8 hole 2.8: 1(0,0)
FTP_118
  round 3 hole 1.5: 1(0,-11) 2(0,11)
FTP_120
  round 2.2 hole 1.1: 1(-3.75,1.3) 2(3.75,-1.3)
FTP_126
  round 4 hole 2: 1(-20.25,7.5) 2(-20.25,-7.5)
  custom 0.6x0.6 hole 8.3x1.4: 3(17.5,-12.5) 4(17.5,-7.5) 5(17.5,7.5) 6(17.5,12.5)
FTP_128
  rect 0.6x1.46 smd: 1(-3.025,-2.925) 10(3.025,-2.925) 11(3.025,2.925) 20(-3.025,2.925)
  rect 0.4x1.46 smd: 2(-2.275,-2.925) 3(-1.625,-2.925) 4(-0.975,-2.925) 5(-0.325,-2.925) 6(0.325,-2.925) 7(0.975,-2.925) 8(1.625,-2.925) 9(2.275,-2.925) 12(2.275,2.925) 13(1.625,2.925) 14(0.975,2.925) 15(0.325,2.925) 16(-0.325,2.925) 17(-0.975,2.925) 18(-1.625,2.925) 19(-2.275,2.925)
KC00050AKP
  rect 0.45x0.55 smd: 1(-0.425,0) 2(0.425,0)
KC00050AKP#2
  rect 0.45x0.55 smd: 1(0.425,0) 2(-0.425,0)
LOCAL_CTW_67A3_3UH
  oval 10x4.8 hole 9x3.8: F(11.5,-8.25) S(-11.5,8.25)
LOCAL_DC215N
  round 0.01 hole 0.8 unplated: (5.08,0)
  round 5.08 hole 2.6: 1(0,0) 2(10.16,0)
LOCAL_DE2E3SA222MN3AT02F
  round 1.4 hole 0.9: 1(0,0) 2(7.5,0)
LOCAL_ECWF6104JL
  round 1.778 hole 1.2: 1(-0.02,0) 2(14.981,0)
LOCAL_G5PZ_1A
  round 1.5 hole 1: 1(0,0) 4(0,7.5)
  round 1.95 hole 1.3: 2(16.5,0) 3(20,7.5)
LOCAL_I8K0A8
  rect 0.825x1.795 smd: 1(4.582,4.72) 8(-4.582,4.72) 9(-4.582,-4.72) 16(4.582,-4.72)
  rect 0.55x1.795 smd: 2(3.175,4.72) 3(1.905,4.72) 4(0.635,4.72) 5(-0.635,4.72) 6(-1.905,4.72) 7(-3.175,4.72) 10(-3.175,-4.72) 11(-1.905,-4.72) 12(-0.635,-4.72) 13(0.635,-4.72) 14(1.905,-4.72) 15(3.175,-4.72)
LOCAL_SNP100F0AKP
  custom 1.09x1.09 smd: (0,0)
  rect 0.55x1.05 smd: 1(-1.905,-2.975) 2(-0.635,-2.975) 3(0.635,-2.975) 4(1.905,-2.975) 5(1.905,2.975) 6(0.635,2.975) 7(-0.635,2.975) 8(-1.905,2.975)
LOCAL_UCC28910_A
  rect 1.528x0.65 smd: 1(-2.711,1.905) 2(-2.711,0.635) 3(-2.711,-0.635) 4(-2.711,-1.905) 5(2.711,-1.905) 6(2.711,-0.635) 8(2.711,1.905)
LOCAL_YB_03317A
  round 1.5 hole 1: 1(0,0) 2(3.25,0) 3(6.5,0) 4(9.75,0) 5(13,0) 7(9.75,11.4) 8(6.5,11.4) 9(3.25,11.4)
MM01320AKP
  rect 1x2.25 smd: 1(2.3,2.775) 2(0,2.775) 3(-2.3,2.775)
  rect 3.2x2.25 smd: 4(0,-2.775)
MMK01670AKP
  rect 1.212x1.2 smd: A(-1.494,0) C(1.494,0)
RDP10020ATP
  round 1.9 hole 1.65: D(5.44,0) G(0,0) S(10.88,0)
SIK00180ATP
  round 1.4 hole 0.9: 1(0,0) 2(7.5,0)
US2H_A
  custom 0.2x0.2 smd: A(1.25,0)
  rect 2x1.1 smd: C(-0.65,0)

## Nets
P12V: C92.2 C93.2 C100.2 CN6.1 IC8.1 IC8.6 Q15.5 Q15.6 Q15.7 Q15.8 Q16.5 Q16.6 Q16.7 Q16.8 Q17.5 Q17.6 Q17.7 Q17.8 Q18.5 Q18.6 Q18.7 Q18.8 Q19.5 Q19.6 Q19.7 Q19.8 Q20.5 Q20.6 Q20.7 Q20.8 Q21.5 Q21.6 Q21.7 Q21.8 Q22.5 Q22.6 Q22.7 Q22.8 Q23.5 Q23.6 Q23.7 Q23.8 Q24.5 Q24.6 Q24.7 Q24.8
VCC5R0_1: C103.2 IC12.16 R117.2
VCC5R0_2: C104.2 IC12.1 R815.2
VCC12R0_1: C70.2 D48.C IC2.1 IC2.8 IC20.4 R83.2 R87.2 R116.1 R120.1 R121.1 R122.1 R123.1 R832.1 TP82.1
VCC12R0_2: R49.1 R124.1 R125.1 R813.2 R814.1 TP83.1
$BN000001: C1.2 C7.2 C39.2 C800.2 C801.1 C801.2 D1.C D2.C D3.1 D80.C IC3.4 R89.1 R89.2 R90.2 R91.1 R91.2 R92.1 R92.2 R178.1 R178.2 R179.2 R227.1 R227.2 R800.1 R800.2 R801.1 R801.2 R802.1 R802.2 T4.2 T8.1 TP8.1 TP44.1
$BN000002: C38.2 D8.C D9.C IC3.5 R1.1 R1.2 R2.2 R94.1 R94.2 R95.1 R95.2 R228.1 R228.2 TP7.1
CONN002: C19.1 C19.2 D17.C D24.A D40.C D41.A IC4.11 IC4.13 Q3.G Q3.S Q4.D R31.1 R31.2 R126.1 R126.2 R127.1 R127.2 T5.1 T6.1 TP11.1
CONN003: C18.1 C18.2 D16.C D18.C D19.A D23.A D42.C D43.A IC5.11 IC5.13 L3.1 L3.2 Q5.G Q5.S Q6.D R28.1 R28.2 R132.1 R132.2 R133.1 R133.2 T5.2 T6.2 TP13.1 TP15.1
CONN004: C2.2 C3.2 C4.2 C5.2 C6.2 C59.2 C102.2 CN8.1 CN9.1 IC8.7 L5.F L6.F Q15.1 Q15.2 Q15.3 Q16.1 Q16.2 Q16.3 Q17.1 Q17.2 Q17.3 Q18.1 Q18.2 Q18.3 Q19.1 Q19.2 Q19.3 Q20.1 Q20.2 Q20.3 Q21.1 Q21.2 Q21.3 Q22.1 Q22.2 Q22.3 Q23.1 Q23.2 Q23.3 Q24.1 Q24.2 Q24.3 R75.2 R77.1 R106.1 R199.2 R200.2 R201.2 R202.2 R203.2 TP31.1
CS: C26.2 C99.2 D14.C IC10.1 IC10.2 IC10.10 IC10.11 IC10.12 IC10.13 IC10.14 IC10.15 R44.1 R44.2 R45.2 R55.2 R56.2 R57.1 R57.2 R58.1 R58.2 R59.1 R59.2 R60.1 R60.2 R61.2 R62.1 R62.2 R63.1 R63.2 R64.2 R65.1 R65.2 R66.2 R67.1 R67.2 R69.1 R69.2 R70.2 R184.2 R185.2 R207.1 R207.2 R208.2 R209.2 R210.1 R210.2 R211.1 R211.2 TP46.1
CSA: C76.2 D13.C D33.C IC3.9 R7.2 R87.1 R170.1 R170.2 TP2.1
CSB: C75.2 D12.C D31.C IC3.8 R8.2 R83.1 R169.1 R169.2 TP1.1
FG1: CN1.2
FG2: C79.1
FG3: C32.1 C78.1
FG4: C31.1 C63.1 C64.1
FG5: C101.2 R805.2
FG6: C93.1 C94.2 R205.1 R206.1
FG7: R204.1
GDA: C81.2 IC2.2 IC3.14 TP5.1
GDB: C80.2 IC2.4 IC3.17 TP6.1
HS1_1: R224.2
HS1_2: R225.2
LGND: C2.1 C3.1 C4.1 C5.1 C6.1 C23.1 C24.1 C25.1 C26.1 C27.1 C51.1 C60.1 C61.1 C88.1 C89.1 C90.1 C91.1 C92.1 C94.1 C99.1 C100.1 C102.1 C104.1 C816.1 C817.1 C818.1 CN7.1 CN8.2 CN9.2 CN10.2 D26.A D27.A D28.A D29.A IC6.3 IC7.3 IC8.3 IC8.4 IC10.24 IC12.2 IC12.8 IC82.2 Q7.1 Q7.2 Q7.3 Q8.1 Q8.2 Q8.3 Q9.1 Q9.2 Q9.3 Q10.1 Q10.2 Q10.3 Q11.1 Q11.2 Q11.3 Q12.1 Q12.2 Q12.3 Q13.1 Q13.2 Q13.3 Q14.1 Q14.2 Q14.3 Q25.1 Q25.2 Q25.3 Q26.1 Q26.2 Q26.3 Q27.1 Q27.2 Q27.3 Q28.1 Q28.2 Q28.3 R9.1 R19.1 R21.1 R22.1 R25.1 R43.1 R45.1 R48.1 R50.1 R51.1 R52.1 R53.1 R54.1 R55.1 R56.1 R61.1 R64.1 R66.1 R70.1 R76.1 R105.1 R180.1 R181.1 R182.1 R184.1 R185.1 R199.1 R200.1 R201.1 R202.1 R203.1 R204.2 R205.2 R206.2 R208.1 R209.1 R805.1 R812.1 R817.1 R821.1 R825.1 R829.1 T4.3 T8.7 TP41.1 TP42.1
OUTA1: C54.2 IC5.1 IC12.14 R111.1 R111.2 TP38.1
OUTA2: IC10.22 IC12.3 R816.1 R816.2 R817.2 R819.1 R819.2 TP34.1
OUTB1: C53.2 IC5.2 IC12.13 R110.1 R110.2 TP39.1
OUTB2: IC10.21 IC12.4 R820.1 R820.2 R821.2 R823.1 R823.2 TP35.1
OUTC1: C57.2 IC4.1 IC12.12 R113.1 R113.2 TP9.1
OUTC2: IC10.20 IC12.5 R824.1 R824.2 R825.2 R827.1 R827.2 TP36.1
OUTD1: C56.2 IC4.2 IC12.11 R112.1 R112.2 TP10.1
OUTD2: IC10.19 IC12.6 R828.1 R828.2 R829.2 R831.1 R831.2 TP37.1
OUTE: IC6.2 IC7.2 IC10.18 TP23.1
OUTF: IC6.4 IC7.4 IC10.17 TP24.1
PN: C1.1 C7.1 C34.1 C35.1 C36.1 C37.1 C38.1 C39.1 C40.1 C42.1 C43.1 C45.1 C47.1 C48.1 C49.1 C50.1 C53.1 C54.1 C55.1 C56.1 C57.1 C58.1 C62.1 C66.1 C67.1 C70.1 C75.1 C76.1 C77.1 C80.1 C81.1 C82.1 C83.1 C84.1 C85.1 C86.1 C87.1 C101.1 C103.1 C800.1 C802.1 C803.1 C804.1 C805.1 C806.1 C808.1 D3.4 D18.A D22.A D25.A D48.A D49.A IC2.3 IC3.16 IC4.3 IC4.5 IC5.3 IC5.5 IC11.2 IC12.9 IC12.15 IC20.1 IC80.1 IC80.2 IC80.3 Q1.S Q2.S Q4.S Q6.S R2.1 R7.1 R8.1 R29.1 R33.1 R71.1 R73.1 R90.1 R93.1 R96.1 R98.1 R99.1 R100.1 R101.1 R102.1 R103.1 R104.1 R174.1 R175.1 R176.1 R179.1 R198.1 R220.1 R221.1 R222.1 R223.1 R224.1 R225.1 R803.1 R804.1 R806.1 R807.1 R811.1 T2.2 T3.2 T8.4 TP43.1 TP45.1
SIG1: C30.1 C30.2 C78.2 C79.2 CN1.3 F1.2 IC1.2 IC1.3 IC1.6 IC1.7 L11.2 L11.3 R79.1 R79.2 R80.1 R80.2 RV1.1 RV1.2
SIG6: C33.1 C33.2 C63.2 C64.2 C65.1 C65.2 D1.A D2.A D3.2 D3.3 D8.A D9.A IC20.2 IC20.3 L1.1 L1.2 L2.1 L2.2 L12.1 L12.4 R138.1 R138.2 T2.4 T3.4
SIG15: C34.2 D12.A R81.1 R81.2 T2.1
SIG18: Q2.D T2.3
SIG20: C36.2 D13.A R85.1 R85.2 T3.1
SIG22: Q1.D T3.3
SIG23: D36.C D37.A FB1.1 FB1.2 Q2.G R71.2 R72.1 R72.2 R108.1 R108.2 TP3.1
SIG24: C35.2 D30.A D30.C D31.A D36.A D37.C IC2.5 R82.1 R82.2 R172.1 R172.2
SIG25: C37.2 D32.A D32.C D33.A D38.A D39.C IC2.7 R86.1 R86.2 R173.1 R173.2
SIG27: D38.C D39.A FB2.1 FB2.2 Q1.G R73.2 R74.1 R74.2 R109.1 R109.2 TP4.1
SIG43: C45.2 C46.1 C46.2 IC3.11 R99.2
SIG45: C43.2 C44.1 C44.2 IC3.12 R98.2
SIG47: C40.2 C41.1 C41.2 IC3.3 R93.2
SIG50: C49.2 IC3.18
SIG0052: D53.C D54.A Q13.4 Q14.4 Q26.4 R20.1 R20.2 R21.2 R213.1 R213.2 TP19.1
SIG52: IC3.19 R100.2 R198.2
SIG0053: D51.C D52.A Q11.4 Q12.4 Q25.4 R18.1 R18.2 R19.2 R212.1 R212.2 TP21.1
SIG53: IC3.7 R101.2 R176.2
SIG0054: D55.C D56.A Q7.4 Q8.4 Q28.4 R22.2 R23.1 R23.2 R214.1 R214.2 TP22.1
SIG54: IC3.6 R102.2 R175.2
SIG0055: D57.C D58.A Q9.4 Q10.4 Q27.4 R24.1 R24.2 R25.2 R215.1 R215.2 TP20.1
SIG55: IC3.20 R103.2 R174.2
SIG56: IC3.2 R104.2
SIG82: D46.C D47.A Q6.G R29.2 R136.1 R136.2 R137.1 R137.2 TP14.1
SIG86: C47.2 C48.2 D49.C IC3.15 R120.2
SIG91: C58.2 C84.2 C85.2 D17.A IC4.7 R115.1 R115.2 R122.2
SIG95: C55.2 C86.2 C87.2 D16.A IC5.7 R114.1 R114.2 R123.2
SIG104: C62.2 C82.2 C83.2 IC2.6 R121.2
SIG115: D34.A Q9.5 Q9.6 Q9.7 Q9.8 Q10.5 Q10.6 Q10.7 Q10.8 Q27.5 Q27.6 Q27.7 Q27.8 T5.5
SIG116: D29.C D57.A D58.C IC7.7
SIG117: D28.C D55.A D56.C IC7.5
SIG121: C60.2 C90.2 C91.2 IC7.6 R124.2
SIG122: C59.1 IC8.8
SIG124: C61.2 C88.2 C89.2 IC6.6 R125.2
SIG126: D26.C D53.A D54.C IC6.7
SIG127: D27.C D51.A D52.C IC6.5
SIG134: D20.A Q13.5 Q13.6 Q13.7 Q13.8 Q14.5 Q14.6 Q14.7 Q14.8 Q26.5 Q26.6 Q26.7 Q26.8 T6.5 TP29.1
SIG135: D21.A Q11.5 Q11.6 Q11.7 Q11.8 Q12.5 Q12.6 Q12.7 Q12.8 Q25.5 Q25.6 Q25.7 Q25.8 T6.6 TP30.1
SIG136: IC8.5 Q15.4 Q16.4 Q17.4 Q18.4 Q19.4 Q20.4 Q21.4 Q22.4 Q23.4 Q24.4 R6.1 R6.2 TP28.1
SIG138: C27.2 D20.C D21.C R76.2 R77.2 TP27.1
SIG148: IC10.6 R51.2 R180.2
SIG149: IC10.7 R52.2 R181.2
SIG150: IC10.8 R53.2 R182.2
SIG151: IC10.9 R54.2
SIG152: C25.2 CN10.1 IC10.5 R50.2
SIG156: C20.1 C20.2 C21.1 C21.2 C22.1 C22.2 IC10.3 IC10.4 R42.1 R42.2 R43.2 R46.1 R46.2 R47.1 R47.2 R48.2 R75.1 TP32.1 TP33.1
SIG183: C23.2 C24.2 IC10.23 R49.2
SIG185: C67.2 IC11.5 R117.1
SIG193: CN1.1 F1.1
SIG199: C31.2 C32.2 C52.1 C52.2 L11.1 L11.4 L12.2 L12.3
SIG205: D44.C D45.A Q4.G R33.2 R134.1 R134.2 R135.1 R135.2 TP12.1
SIG223: C66.2 IC11.1 IC11.3 R116.2
SIG00817: HS1.1 R220.2
SIG00818: HS2.1 R221.2
SIG00819: HS3.1 R222.2
SIG00820: HS4.1 R223.2
SIG00821: C805.2 C806.2 D83.A D84.A D84.C IC81.1 IC81.2 IC81.4 R810.1 R810.2 R811.2 R832.2
SIG00822: C804.2 C808.2 D82.C D83.C IC81.3
SIG00823: C818.2 IC82.5 R815.1
SIG00826: C817.2 IC82.1 IC82.3 R814.2
SIG00828: C802.2 C803.2 D81.C IC80.6 R809.1 R809.2
SIG00829: C815.1 C815.2 D90.A R812.2 T8.9
SIG00831: D81.A D82.A IC80.5 R806.2 R807.2 R808.1 R808.2 T8.5
SIG00832: IC80.4 R803.2 R804.2
SIG00834: D80.A IC80.8 T8.3
SIG00840: C816.2 D90.C R813.1
SIGN269: D23.C D42.A D43.C IC5.12
SIGN273: C51.2 D34.C D35.C R105.2 R106.2
SIGN318: D24.C D40.A D41.C IC4.12
SIGN322: D22.C D46.A D47.C IC5.6
SIGN325: D25.C D44.A D45.C IC4.6
SIGN355: D19.C Q3.D Q5.D T4.1
SIGN356: D14.A R9.2 T4.5
SIGN360: L5.S T5.3 T5.4 TP18.1
SIGN361: D35.A Q7.5 Q7.6 Q7.7 Q7.8 Q8.5 Q8.6 Q8.7 Q8.8 Q28.5 Q28.6 Q28.7 Q28.8 T5.6
SIGN362: L6.S T6.3 T6.4 TP17.1
VREF_PFC: C42.2 C50.2 C77.2 IC3.1 IC3.10 IC3.13 R96.2 R97.1 R97.2 R171.1 R171.2 R177.1 R177.2

Pads without a net: D22 NC; D23 NC; D24 NC; D25 NC; D26 NC; D27 NC; D28 NC; D29 NC; D84 NC; IC1 1 4 5 8; IC4 4 8 9 10 14; IC5 4 8 9 10 14; IC6 1 8; IC7 1 8; IC8 2; IC10 16; IC11 4; IC12 7 10; IC82 4; T4 4 6 7; T8 2 8

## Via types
v1: diameter 0.55, hole 0.3, TOP to BOTTOM, 296 vias
v2: diameter 1.397, hole 0.8, TOP to BOTTOM, 225 vias
v3: diameter 6, hole 3.3, TOP to BOTTOM, 6 vias
v4: diameter 7, hole 3.2, TOP to BOTTOM, 4 vias
v5: diameter 10, hole 4.2, TOP to BOTTOM, 1 via

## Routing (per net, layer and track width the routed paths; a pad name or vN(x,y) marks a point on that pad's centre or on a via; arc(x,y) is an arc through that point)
P12V: length 123
  TOP w2.3: v3(281.5,60.5) 281.5,64.25 ; v3(281.5,60.5) 285.3,60.5 ; v3(281.5,60.5) v3(281.5,54) ; v3(281.5,60.5) 276.75,60.5 ; CN6.1 297.5,50.6 ; CN6.1 v3(297.5,60.5) ; CN6.1 294.15,54 ; CN6.1 300.85,54 ; v3(297.5,60.5) 294.1,60.5 ; v3(297.5,60.5) 301.15,60.5 ; v3(297.5,60.5) 297.5,64.2 ; v3(281.5,54) 277.95,54 ; v3(281.5,54) 284.6,54 ; v3(281.5,54) 281.5,49.65
  CONDUCTIVE3 w2.3: CN6.1 293.95,54 ; CN6.1 300.85,54 ; CN6.1 297.5,49.6 ; CN6.1 v3(297.5,60.5) ; v3(297.5,60.5) 293.4,60.5 ; v3(297.5,60.5) 300.95,60.5 ; v3(297.5,60.5) 297.5,64.9 ; v3(281.5,60.5) 285.55,60.5 ; v3(281.5,60.5) 281.5,64.9 ; v3(281.5,60.5) 278.25,60.5 ; v3(281.5,60.5) v3(281.5,54) ; v3(281.5,54) 277.65,54 ; v3(281.5,54) 284.3,54 ; v3(281.5,54) 281.5,49.6
  BOTTOM w0.45: 269.51,41.29 269.51,40.38 270.3,39.6 271.35,39.6 272.19,38.76 272.19,37.81
  BOTTOM w0.55: IC8.6 269.51,41.29
  BOTTOM w0.825: 272.19,37.81 IC8.1
  vias: v2(279.1,70.4) v2(279.1,67.4) v2(281.1,68.9) v2(281.1,65.9) v2(283.1,70.4) v2(283.1,67.4) v2(285.1,68.9) v2(285.1,65.9) v2(287.1,70.4) v2(287.1,67.4) v2(289.1,68.9) v2(289.1,65.9) v2(291.1,70.4) v2(291.1,67.4) v2(293.1,68.9) v2(293.1,65.9) v2(295.1,70.4) v2(295.1,67.4) v2(297.1,68.9) v2(297.1,65.9) v2(299.1,70.4) v2(299.1,67.4) v2(301.1,68.9) v2(301.1,65.9)
VCC5R0_1: length 14.9
  TOP w0.5: v1(221.54,11.82) 220.2,10.48 220.2,4.45 219,3.25 v1(217.7,3.25)
  BOTTOM w0.5: v1(217.7,3.25) 217.5,3.05 R117.2 ; 220.43,11.82 v1(221.54,11.82)
  BOTTOM w0.825: IC12.16 220.43,11.82
VCC5R0_2: length 5
  TOP w0.5: R815.2 238.07,17.5 v1(238.07,16.72)
  BOTTOM w0.3: 229.87,11.82 231.16,11.82 C104.2 231.97,12.19 v1(231.97,12.76)
  BOTTOM w0.825: IC12.1 229.87,11.82
VCC12R0_1: length 113.5
  TOP w0.3: 131.25,1.92 131.25,5.51 v1(131.5,5.76)
  TOP w0.45: R123.1 145.28,102.58 141.45,98.75 v1(141.45,98.05) v1(141.45,96.8)
  TOP w0.5: R122.1 173.78,68 173.78,54.45 176.03,52.2 176.03,45.87 180.9,41 180.9,33.45 v1(183.05,31.3) ; IC20.4 93.48,66.42 v1(107.44,66.42)
  TOP w2.1: TP82.1 131.25,1.92
  CONDUCTIVE3 w0.3: v1(107.44,66.42) 107.44,58.42 115.56,50.3 v1(124.46,50.3) v1(126.4,50.3)
  CONDUCTIVE4 w1: v1(141.45,98.05) v1(141.45,96.8)
  BOTTOM w0.3: v1(131.5,5.76) 135.05,5.76
  BOTTOM w0.45: 135.05,5.76 R120.1
  BOTTOM w1: v1(126.4,50.3) v1(124.46,50.3) ; IC20.4 91.59,68.31
  vias: v1(144.7,56.9) v1(144.7,44.9) v1(147.9,46.7) v1(181.22,21.89) v1(181.22,21.14) v1(208.1,7.2) v1(208.1,6.2)
VCC12R0_2: length 51
  TOP w0.3: 237.06,22.65 235.38,22.65 231.71,18.98 230.94,18.98
  TOP w0.45: 230.94,18.98 R814.1
  TOP w0.5: R124.1 228,59.75 226.6,61.15 226.6,66.1 225.5,67.2 v1(223.1,67.2) v1(221.85,67.2)
  TOP w2.1: 237.06,22.65 TP83.1
  CONDUCTIVE3 w1: 230.77,93.17 229.71,92.11 226.51,92.11 ; 224.1,41.63 224.1,52.37 228.3,56.57 228.3,62.35 228.28,62.33
  vias: v1(227,19.6) v1(227.7,18.9) v1(230.78,100.37) v1(230.78,99.6) v1(243.4,15.8)
$BN000001: length 14.3
  TOP w0.3: v1(148.9,8.55) 150.85,8.55 152.8,6.6 155.65,6.6 156.95,5.3 156.95,3.21 157.15,1.65
  TOP w2.1: 157.15,1.65 TP8.1
  vias: v1(134.18,63.81) v1(135.18,63.81) v1(136.18,63.81) v1(165.38,63.81) v1(166.38,63.81) v1(167.38,63.81) v1(170.1,3.55) v1(171.2,3.55) v1(191.15,21.95) v1(191.15,21)
$BN000002: length 211.7
  TOP w0.3: v1(124.9,126.35) v1(126.3,126.35) ; v1(148.9,7.5) 148.35,7.5 148.1,7.25 148.1,5.75 148.8,5.05 149.85,5.05 151.9,3 TP7.1
  CONDUCTIVE3 w0.3: v1(123.55,120.6) 95.6,120.6 85.45,110.45 85.45,98.45 103.7,80.2 103.7,58.6 113,49.3 113,37.75 137.6,13.15 137.6,3.6 139.35,1.85 159.85,1.85 160.45,2.45 v1(160.45,3.45)
  BOTTOM w0.3: v1(123.55,120.6) 125.98,120.6 ; 125.32,120.65 123.5,120.65
  BOTTOM w0.45: 158.53,8.6 R2.2
  BOTTOM w0.92: R94.1 125.32,120.65
CONN002: length 41.4
  CONDUCTIVE4 w0.2: v1(149.5,77.85) 150.72,79.08 155.28,79.08 159.32,75.03 v1(159.32,74.62)
  CONDUCTIVE4 w7: 164.5,94 164.5,108.27 170.32,114.55 172.6,114.55
  BOTTOM w0.3: C19.1 158.72,74.02 v1(159.32,74.62) ; 158.68,72.86 157.99,72.86 157.55,73.3 v1(157.55,74.62)
  BOTTOM w0.45: C19.2 158.68,72.86
  vias: v1(141.52,89) v1(142.52,89) v1(143.52,89) v1(153.4,89) v1(164.36,89) v1(165.36,89) v1(166.36,89)
CONN003: length 50.1
  TOP w0.3: 146.81,121.9 144.95,121.9 ; v1(173.25,121.8) 171.25,123.8 167.09,123.8 ; 132.95,129.4 133.75,130.75 134.3,131.3 Q5.G ; 145.02,122.1 147.23,122.1
  TOP w0.92: R132.1 145.02,122.1
  TOP w1.1: D42.C 146.81,121.9
  TOP w2.1: 132.95,129.4 TP13.1 ; TP15.1 167.09,123.8
  CONDUCTIVE3 w0.3: 164.34,123.3 164.34,121.8 v1(173.25,121.8)
  CONDUCTIVE3 w5: 161.15,108.2 161.15,123.21 158.65,123.21
  BOTTOM w0.3: 151.95,122.43 v1(151.95,120.65)
  BOTTOM w1.1: D16.C 151.95,122.43
  vias: v1(137.5,129.8) v1(147.38,129.8) v1(148.38,129.8) v1(149.38,129.8) v1(156.9,107) v1(157.6,107.7) v1(157.6,107) v1(158.3,108.4) v1(158.3,107.7) v1(158.3,107) v1(159.84,129.8) v1(160.84,129.8) v1(161.84,129.8)
CONN004: length 420.3
  TOP w1: R77.1 253.6,124.6 ; R77.1 253.6,128.93 ; R77.1 255.47,126.7 ; 280.5,121 C2.2 ; C2.2 282.5,123 ; C2.2 278.5,123 ; R106.1 257.4,75.13 ; R106.1 257.4,71.01 ; R106.1 255.2,73.1 ; R106.1 259.49,73.1 ; 293.5,88 C6.2 ; C6.2 295.5,90 ; C6.2 295.5,86 ; 292.47,121.15 292.47,122.99 ; 294,100.5 C5.2 ; C5.2 296.5,99 ; C5.2 296.5,102.5 ; 296.5,114.5 C4.2 ; C4.2 294.5,112.5 ; C4.2 296.5,110.5 ; 290.63,122.97 294.62,122.97
  TOP w1.5: CN9.1 269.96,122.9 ; 263.91,123.05 CN8.1 261.64,125.27
  TOP w2.5: 263.05,104.5 L6.F 263.05,117.66 ; 258.55,53.9 L5.F 258.55,66.19
  TOP w5: 258.69,111.4 L6.F 267.07,111.4 ; 261.54,59.8 L5.F 256.03,59.8
  CONDUCTIVE3 w1: C6.2 295.5,89.65 ; C6.2 295.5,86.35 ; C6.2 293.85,88 ; C6.2 297.15,88 ; C5.2 294.85,100.5 ; C5.2 296.5,102.15 ; C5.2 296.5,98.85 ; C3.2 290.85,123 ; C3.2 292.5,121.35 ; C3.2 294.15,123 ; R77.1 253.6,124.75 ; R77.1 253.6,128.65 ; R77.1 255.55,126.7 ; R106.1 257.4,70.53 ; R106.1 257.4,75.6 ; R106.1 259.69,73.1 ; R106.1 255.06,73.1 ; C4.2 296.5,110.85 ; C4.2 296.5,114.15 ; C4.2 294.85,112.5 ; C2.2 280.5,121.35 ; C2.2 282.15,123 ; C2.2 278.85,123
  CONDUCTIVE3 w2.5: 258.55,54.26 L5.F 258.55,66.5 ; 263.05,117.93 L6.F 263.05,102.52
  CONDUCTIVE3 w5: 263.45,59.8 L5.F 256.04,59.8 ; 257.25,111.4 L6.F 267.78,111.4
  CONDUCTIVE4 w1: v2(274,83.5) 272.77,83.5 269.65,80.38 269.65,52.7 265.6,48.65 265.6,46.95 267.85,44.7 270.15,44.7 ; C4.2 296.5,114.49 ; C4.2 296.5,110.16 ; C4.2 294.07,112.5 ; R106.1 257.4,70.73 ; R106.1 255.51,73.1 ; R106.1 259.39,73.1 ; R106.1 257.4,75.27 ; C3.2 294.34,123 ; C3.2 290.43,123 ; C3.2 292.5,121.12 ; 270.15,44.7 271.05,43.8 ; 270.15,44.7 v1(271.05,44.7) 271.05,43.8 ; 271.05,43.8 271.05,22.8 v1(265.2,16.95) ; C6.2 295.5,89.88 ; C6.2 293.44,88 ; C6.2 295.5,85.97 ; C6.2 297.62,88 ; R77.1 253.6,124.38 ; R77.1 255.87,126.7 ; R77.1 253.6,129.1 ; C2.2 278.45,123 ; C2.2 282.51,123 ; C2.2 280.5,121.45 ; C5.2 294.01,100.5 ; C5.2 296.5,97.97 ; C5.2 296.5,102.78
  CONDUCTIVE4 w2.5: 258.55,66.97 L5.F 258.55,53.8 ; 263.05,104.14 L6.F 263.05,117.83
  CONDUCTIVE4 w5: 266.6,111.4 L6.F 259.08,111.4 ; 255.9,59.8 L5.F 261.24,59.8
  BOTTOM w0.3: v1(265.2,16.95) 265.2,16
  BOTTOM w0.45: 265.2,16 265.2,15.82
  BOTTOM w1: 293.5,88 C6.2 ; C6.2 295.5,86.5 ; C6.2 295.5,90 ; C3.2 294,123 ; C3.2 292.5,121.5 ; C3.2 291,123 ; 296.5,114.5 C4.2 ; C4.2 296.5,110 ; C4.2 294.5,112.5 ; R77.1 253.6,128.78 ; R77.1 253.6,124.38 ; R77.1 255.71,126.7 ; R106.1 255.17,73.1 ; R106.1 257.4,75.65 ; R106.1 259.85,73.1 ; R106.1 257.4,70.93 ; C2.2 282.5,123 ; C2.2 280.5,121 ; C2.2 278.5,123 ; C5.2 296.5,98.5 ; C5.2 294.5,100.5 ; C5.2 296.5,102.5
  BOTTOM w1.5: 263.91,123.21 CN8.1 260.93,125.27
  BOTTOM w2.5: 263.05,105.3 L6.F 263.05,117.72 ; 258.55,54.16 L5.F 258.55,66.03
  vias: v2(271.3,116.55) v2(273.05,118.35) v2(274,89.5) v2(274,86.5) v2(276,88) v2(276,85) v2(276,82) v2(276.5,118.45) v2(278,116.5) v2(278,89.5) v2(278,86.5) v2(278,83.5) v2(279.5,118.45) v2(280,88) v2(280,85) v2(280,82) v2(281,116.5) v2(282,89.5) v2(282,86.5) v2(282,83.5) v2(282.5,118.45) v2(284,88) v2(284,85) v2(284,82) v2(286,89.5) v2(286,86.5) v2(286,83.5) v2(288,116.5) v2(288,96.5) v2(288,88) v2(288,85) v2(288,82) v2(289.5,118.45) v2(290,111.5) v2(290,108.5) v2(290,105.5) v2(290,101) v2(290,98) v2(290,89.5) v2(290,86.5) v2(290,83.5) v2(291,116.5) v2(292,110) v2(292,107) v2(292,104) v2(292,99.5) v2(292,96.5) v2(292.5,118.45) v2(293.9,116.5) v2(295.5,118.45)
CS: length 84.9
  TOP w0.3: TP46.1 251,7.7 v1(251,9.7)
  TOP w0.45: R207.1 R55.2 ; 249.72,8.1 249.72,6.2
  CONDUCTIVE3 w1: v1(261.2,8.9) v1(261.2,10.2) 261.2,12.7 259.85,14.05 259.85,16.25 ; 245.9,8.5 245.9,15.27 246.48,15.85 255.35,15.85 257,17.5 v1(258.6,17.5) ; 245.9,8.5 245.9,7.9 ; 245.9,8.5 245.3,7.9 ; 259.85,16.25 v1(259.85,17.5) v1(258.6,17.5) ; 259.85,16.25 v1(258.6,17.5) ; v1(244.3,7.9) 245.3,7.9 ; 245.3,7.9 245.9,7.3 ; 245.3,7.9 245.9,7.9 ; 245.9,7.3 245.9,7.9 ; 245.9,7.3 245.9,6.35 244.65,5.1 v1(244.3,5.1)
  CONDUCTIVE4 w0.2: v1(262.25,6.65) 248.85,6.65 242.55,12.95 v1(240.79,12.95)
  BOTTOM w0.3: 248.82,8.82 248.12,8.82 247.45,8.15 v1(247.45,6.5) ; v1(261.2,8.9) v1(261.2,10.2) 259.62,10.2 259.02,9.6 ; R44.1 258.02,16.38 258.2,16.2 258.8,16.2
  BOTTOM w0.45: 258.8,16.2 258.98,16.2
  BOTTOM w0.5: v1(244.3,7.9) R211.2 ; R44.2 258.32,17.23 v1(258.6,17.5) v1(259.85,17.5) ; v1(244.3,5.1) R210.2
  BOTTOM w0.6: IC10.13 248.82,8.82
  vias: v1(247.45,9.3) v1(257,9.6) v1(257,8.2) v1(257,5.4)
CSA: length 131.7
  TOP w0.3: v1(106.85,84.9) 107.23,84.52 108.4,83.5
  TOP w2.1: 108.4,83.5 TP2.1
  CONDUCTIVE3 w0.2: v1(159.2,3.3) 155.3,3.3 154.2,4.4 154.2,27.6 153,28.8 153,42.25 149.22,46.02 132.88,46.02 v1(130.4,48.5) 125,53.9 125,64.85 123.15,66.7 123.15,82.65 121.6,84.2 107.55,84.2 v1(106.85,84.9)
  BOTTOM w0.3: 107.81,88.42 106.92,88.42 106.26,88.3 ; v1(106.85,84.9) 106.26,85.49 106.26,86.16
  BOTTOM w0.55: 108,88.42 107.81,88.42
  BOTTOM w0.895: 106.26,86.16 R7.2 106.26,88.3
CSB: length 101.2
  CONDUCTIVE3 w0.2: v1(126.6,83.65) 127.3,82.95 127.3,81.2 126.85,80.75 126.85,60.35 129,58.2 132.1,58.2 142.5,47.8 149.8,47.8 v1(152.6,45) 156.6,41 156.6,30.29 157.2,29.69 157.2,5.15 v1(157.68,4.67)
  BOTTOM w0.3: 128.81,86.92 127.92,86.92 127.26,86.8
  BOTTOM w0.55: 129,86.92 128.81,86.92
  BOTTOM w0.895: 127.26,86.8 R8.2
FG1:
  vias: v5(37.5,53.5)
FG2:
  vias: v4(8,4)
FG4: length 11.1
  BOTTOM w1.5: C63.1 C64.1
  BOTTOM w2: C31.1 v4(79.3,4)
FG5: length 5.6
  TOP w0.3: C101.2 191.32,129.46 R805.2
  BOTTOM w0.5: C101.2 189,129.46
FG7:
  vias: v4(302.5,129)
GDA: length 46.7
  TOP w0.3: 146.25,1.65 146.65,3.17 146.65,5.8 v1(145.9,6.55)
  TOP w2.1: 146.25,1.65 TP5.1 145,1.65
  CONDUCTIVE3 w0.2: v1(148.7,42.62) 148.7,41.6 142.8,35.7 142.8,9.05 145.3,6.55 v1(145.9,6.55)
GDB: length 49.7
  TOP w0.3: 139.15,1.65 141.05,1.65 142.3,2.9 142.3,5.25 145.6,8.55 v1(145.9,8.55)
  TOP w2.1: 139.15,1.65 137.9,1.65
  CONDUCTIVE3 w0.2: v1(145.9,8.55) 143.5,10.95 143.5,35.59 149.77,41.87 v1(149.77,42.39)
HS1_2: length 6.6
  TOP w0.5: v4(90.5,129) R225.2
